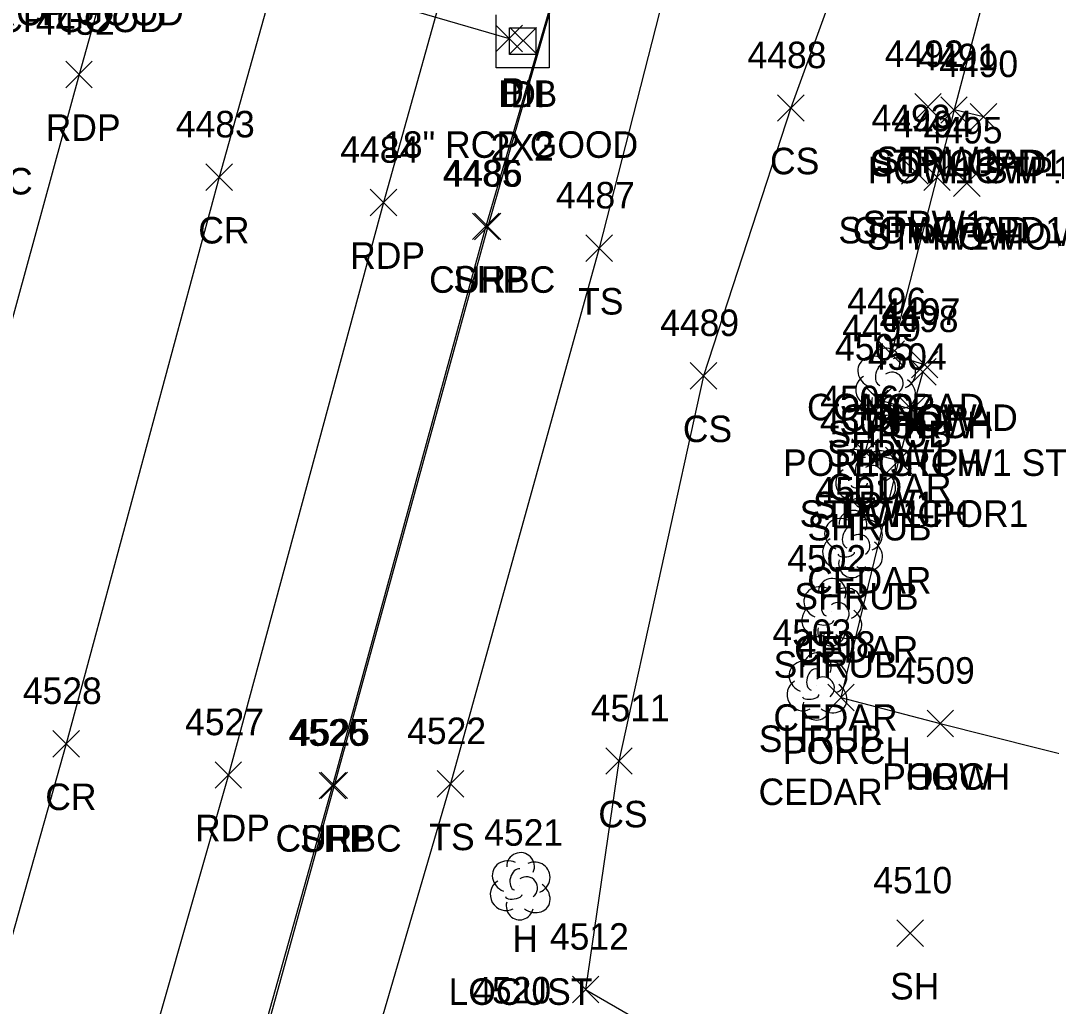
# Model space of a CAD drawing. Extents: x 1443912 to 1445411, y 621446 to 623693.
# Drawn here: x 1444910.4 to 1444988.1, y 623164.8 to 623239.1 of the extents above; entities that cross this region are included whole.
import ezdxf

# ---------------------------------------------------------------- set-up
doc = ezdxf.new("R2010")
doc.units = 0
for name, color, linetype in [('D_A', 7, 'Continuous'), ('D_C', 7, 'Continuous'), ('D_TIC', 7, 'Continuous'), ('DCP', 7, 'Continuous'), ('DS', 7, 'Continuous'), ('L_A', 7, 'Continuous'), ('L_C', 7, 'Continuous'), ('L_I', 7, 'Continuous'), ('L_TIC', 7, 'Continuous'), ('LBC', 7, 'Continuous'), ('LBF', 7, 'Continuous'), ('LELB', 7, 'Continuous'), ('LS', 7, 'Continuous'), ('LSH', 7, 'Continuous'), ('LTD', 7, 'Continuous'), ('P_A', 7, 'Continuous'), ('P_I', 7, 'Continuous'), ('P_TIC', 7, 'Continuous'), ('PET', 7, 'Continuous'), ('PRC', 7, 'Continuous'), ('PSP', 7, 'Continuous'), ('R_A', 7, 'Continuous'), ('R_I', 7, 'Continuous'), ('R_TIC', 7, 'Continuous'), ('RC', 7, 'Continuous')]:
    doc.layers.add(name, color=color, linetype=linetype)

msp = doc.modelspace()

# ---------------------------------------------------------------- linework, layer by layer
at = {"layer": 'D_TIC'}
for points in [[(1444946.257, 623236.76), (1444948.257, 623238.76)], [(1444948.257, 623236.76), (1444946.257, 623238.76)], [(1444947.315, 623236.598), (1444949.315, 623238.598)], [(1444949.315, 623236.598), (1444947.315, 623238.598)]]:
    msp.add_lwpolyline(points, dxfattribs=at)
at = {"layer": 'DCP'}
msp.add_lwpolyline([(1444912.99, 623247.747), (1444947.257, 623237.76)], dxfattribs=at)
at = {"layer": 'DS'}
for p, q in [((1444946.277, 623235.557), (1444946.277, 623239.557)), ((1444950.277, 623239.557), (1444950.277, 623235.557)), ((1444947.277, 623236.557), (1444947.277, 623238.557)), ((1444947.277, 623238.557), (1444949.277, 623238.557)), ((1444949.277, 623238.557), (1444949.277, 623236.557)), ((1444948.283, 623237.559), (1444948.283, 623237.559)), ((1444948.283, 623237.559), (1444948.283, 623237.559)), ((1444949.277, 623236.557), (1444947.277, 623236.557)), ((1444950.277, 623235.557), (1444946.277, 623235.557))]:
    msp.add_line(p, q, dxfattribs=at)
at = {"layer": 'L_TIC'}
for points in [[(1444967.484, 623231.521), (1444969.484, 623233.521)], [(1444969.484, 623231.521), (1444967.484, 623233.521)], [(1444977.831, 623231.611), (1444979.831, 623233.611)], [(1444979.831, 623231.611), (1444977.831, 623233.611)], [(1444979.793, 623231.369), (1444981.793, 623233.369)], [(1444981.793, 623231.369), (1444979.793, 623233.369)], [(1444979.793, 623231.369), (1444981.793, 623233.369)], [(1444981.793, 623231.369), (1444979.793, 623233.369)], [(1444982.02, 623230.85), (1444984.02, 623232.85)], [(1444984.02, 623230.85), (1444982.02, 623232.85)], [(1444982.02, 623230.85), (1444984.02, 623232.85)], [(1444984.02, 623230.85), (1444982.02, 623232.85)], [(1444976.835, 623226.768), (1444978.835, 623228.768)], [(1444978.835, 623226.768), (1444976.835, 623228.768)], [(1444978.509, 623226.308), (1444980.509, 623228.308)], [(1444980.509, 623226.308), (1444978.509, 623228.308)], [(1444978.509, 623226.308), (1444980.509, 623228.308)], [(1444980.509, 623226.308), (1444978.509, 623228.308)], [(1444980.755, 623225.845), (1444982.755, 623227.845)], [(1444982.755, 623225.845), (1444980.755, 623227.845)], [(1444980.755, 623225.845), (1444982.755, 623227.845)], [(1444982.755, 623225.845), (1444980.755, 623227.845)], [(1444953.045, 623220.944), (1444955.045, 623222.944)], [(1444955.045, 623220.944), (1444953.045, 623222.944)], [(1444975.062, 623212.967), (1444977.062, 623214.967)], [(1444977.062, 623212.967), (1444975.062, 623214.967)], [(1444977.578, 623212.165), (1444979.578, 623214.165)], [(1444979.578, 623212.165), (1444977.578, 623214.165)], [(1444977.578, 623212.165), (1444979.578, 623214.165)], [(1444979.578, 623212.165), (1444977.578, 623214.165)], [(1444960.908, 623211.324), (1444962.908, 623213.324)], [(1444962.908, 623211.324), (1444960.908, 623213.324)], [(1444977.439, 623211.62), (1444979.439, 623213.62)], [(1444979.439, 623211.62), (1444977.439, 623213.62)], [(1444977.439, 623211.62), (1444979.439, 623213.62)], [(1444979.439, 623211.62), (1444977.439, 623213.62)], [(1444974.156, 623209.478), (1444976.156, 623211.478)], [(1444976.156, 623209.478), (1444974.156, 623211.478)], [(1444976.627, 623208.775), (1444978.627, 623210.775)], [(1444978.627, 623208.775), (1444976.627, 623210.775)], [(1444976.627, 623208.775), (1444978.627, 623210.775)], [(1444978.627, 623208.775), (1444976.627, 623210.775)], [(1444973.096, 623205.579), (1444975.096, 623207.579)], [(1444975.096, 623205.579), (1444973.096, 623207.579)], [(1444975.619, 623204.932), (1444977.619, 623206.932)], [(1444977.619, 623204.932), (1444975.619, 623206.932)], [(1444975.619, 623204.932), (1444977.619, 623206.932)], [(1444977.619, 623204.932), (1444975.619, 623206.932)], [(1444971.269, 623187.062), (1444973.269, 623189.062)], [(1444973.269, 623187.062), (1444971.269, 623189.062)], [(1444978.759, 623185.106), (1444980.759, 623187.106)], [(1444980.759, 623185.106), (1444978.759, 623187.106)], [(1444978.759, 623185.106), (1444980.759, 623187.106)], [(1444980.759, 623185.106), (1444978.759, 623187.106)], [(1444954.534, 623182.272), (1444956.534, 623184.272)], [(1444956.534, 623182.272), (1444954.534, 623184.272)], [(1444941.825, 623180.553), (1444943.825, 623182.553)], [(1444943.825, 623180.553), (1444941.825, 623182.553)], [(1444976.485, 623169.293), (1444978.485, 623171.293)], [(1444978.485, 623169.293), (1444976.485, 623171.293)], [(1444952.019, 623165.045), (1444954.019, 623167.045)], [(1444954.019, 623165.045), (1444952.019, 623167.045)]]:
    msp.add_lwpolyline(points, dxfattribs=at)
at = {"layer": 'LBC'}
msp.add_lwpolyline([(1444979.759, 623186.106), (1444998.515, 623181.371)], dxfattribs=at)
at = {"layer": 'LBF'}
for points in [[(1444983.02, 623231.85), (1444980.793, 623232.369)], [(1444978.439, 623212.62), (1444977.627, 623209.775), (1444976.619, 623205.932), (1444972.269, 623188.062), (1444979.759, 623186.106)], [(1444977.627, 623209.775), (1444975.156, 623210.478), (1444974.096, 623206.579), (1444976.619, 623205.932)]]:
    msp.add_lwpolyline(points, dxfattribs=at)
at = {"layer": 'LELB'}
for points in [[(1445011.818, 623244.379), (1444995.904, 623251.684), (1444976.44, 623254.406), (1444961.702, 623251.968), (1444954.045, 623221.944), (1444942.825, 623181.553), (1444935.094, 623155.078), (1444941.304, 623148.676), (1444957.21, 623141.482), (1444982.161, 623136.484)], [(1444976.44, 623254.406), (1444968.484, 623232.521), (1444961.908, 623212.324), (1444955.534, 623183.272), (1444953.019, 623166.045), (1444969.926, 623156.274), (1444977.618, 623143.302)]]:
    msp.add_lwpolyline(points, dxfattribs=at)
at = {"layer": 'LS'}
msp.add_lwpolyline([(1444987.132, 623246.17), (1444984.639, 623246.949), (1444980.793, 623232.369), (1444979.509, 623227.308), (1444976.062, 623213.967), (1444978.578, 623213.165)], dxfattribs=at)
at = {"layer": 'LSH'}
for p, q in [((1444975.628, 623211.936), (1444975.628, 623211.936)), ((1444975.628, 623211.936), (1444975.628, 623211.936)), ((1444974.114, 623204.907), (1444974.114, 623204.907)), ((1444974.114, 623204.907), (1444974.114, 623204.907)), ((1444973.125, 623199.696), (1444973.125, 623199.696)), ((1444973.125, 623199.696), (1444973.125, 623199.696)), ((1444971.561, 623194.557), (1444971.561, 623194.557)), ((1444971.561, 623194.557), (1444971.561, 623194.557)), ((1444970.444, 623188.955), (1444970.444, 623188.955)), ((1444970.444, 623188.955), (1444970.444, 623188.955))]:
    msp.add_line(p, q, dxfattribs=at)
for centre in [(1444975.675, 623213.37), (1444974.161, 623206.341), (1444973.172, 623201.13), (1444971.607, 623195.991), (1444970.491, 623190.389)]:
    msp.add_arc(centre, 1.047, 335.52715, 180.95627, dxfattribs=at)
for centre, major_axis, ratio, start_param, end_param in [((1444974.836, 623212.602), (1.21, -0.512), 0.895232, 1.570796, 4.712389), ((1444976.669, 623212.519), (-1.141, -0.483), 0.949671, 1.570796, 4.712389), ((1444975.419, 623212.394), (-0.208, -0.792), 0.645439, 3.141593, 6.283185), ((1444974.545, 623211.227), (0.584, -1.042), 0.959034, 3.141593, 6.283185), ((1444976.128, 623211.769), (-0.5, 0.667), 0.989748, 3.141593, 6.283185), ((1444976.628, 623211.103), (-1.09, 0.792), 0.841452, 1.570796, 4.712389), ((1444975.628, 623210.436), (0.265, 1.061), 0.942809, 1.570796, 4.712389), ((1444975.17, 623211.186), (-0.625, -0.083), 0.423636, 0, 3.141593), ((1444973.323, 623205.573), (1.21, -0.512), 0.895232, 1.570796, 4.712389), ((1444975.156, 623205.49), (-1.141, -0.483), 0.949671, 1.570796, 4.712389), ((1444973.906, 623205.365), (-0.208, -0.792), 0.645439, 3.141593, 6.283185), ((1444973.031, 623204.198), (0.584, -1.042), 0.959034, 3.141593, 6.283185), ((1444974.614, 623204.74), (-0.5, 0.667), 0.989748, 3.141593, 6.283185), ((1444975.115, 623204.074), (-1.09, 0.792), 0.841452, 1.570796, 4.712389), ((1444974.115, 623203.407), (0.265, 1.061), 0.942809, 1.570796, 4.712389), ((1444973.656, 623204.157), (-0.625, -0.083), 0.423636, 0, 3.141593), ((1444972.333, 623200.362), (1.21, -0.512), 0.895232, 1.570796, 4.712389), ((1444974.167, 623200.279), (-1.141, -0.483), 0.949671, 1.570796, 4.712389), ((1444972.917, 623200.154), (-0.208, -0.792), 0.645439, 3.141593, 6.283185), ((1444972.042, 623198.987), (0.584, -1.042), 0.959034, 3.141593, 6.283185), ((1444973.625, 623199.529), (-0.5, 0.667), 0.989748, 3.141593, 6.283185), ((1444974.125, 623198.862), (-1.09, 0.792), 0.841452, 1.570796, 4.712389), ((1444972.667, 623198.945), (-0.625, -0.083), 0.423636, 0, 3.141593), ((1444973.125, 623198.196), (0.265, 1.061), 0.942809, 1.570796, 4.712389), ((1444970.769, 623195.223), (1.21, -0.512), 0.895232, 1.570796, 4.712389), ((1444971.352, 623195.015), (-0.208, -0.792), 0.645439, 3.141593, 6.283185), ((1444972.602, 623195.14), (-1.141, -0.483), 0.949671, 1.570796, 4.712389), ((1444972.061, 623194.39), (-0.5, 0.667), 0.989748, 3.141593, 6.283185), ((1444970.477, 623193.848), (0.584, -1.042), 0.959034, 3.141593, 6.283185), ((1444972.561, 623193.724), (-1.09, 0.792), 0.841452, 1.570796, 4.712389), ((1444971.102, 623193.807), (-0.625, -0.083), 0.423636, 0, 3.141593), ((1444971.561, 623193.057), (0.265, 1.061), 0.942809, 1.570796, 4.712389), ((1444969.652, 623189.622), (1.21, -0.512), 0.895232, 1.570796, 4.712389), ((1444971.485, 623189.539), (-1.141, -0.483), 0.949671, 1.570796, 4.712389), ((1444970.235, 623189.413), (-0.208, -0.792), 0.645439, 3.141593, 6.283185), ((1444970.944, 623188.789), (-0.5, 0.667), 0.989748, 3.141593, 6.283185), ((1444969.361, 623188.247), (0.584, -1.042), 0.959034, 3.141593, 6.283185), ((1444971.444, 623188.122), (-1.09, 0.792), 0.841452, 1.570796, 4.712389), ((1444969.986, 623188.205), (-0.625, -0.083), 0.423636, 0, 3.141593), ((1444970.444, 623187.455), (0.265, 1.061), 0.942809, 1.570796, 4.712389)]:
    msp.add_ellipse(centre, major_axis=major_axis, ratio=ratio, start_param=start_param, end_param=end_param, dxfattribs=at)
at = {"layer": 'LTD'}
msp.add_line((1444948.067, 623173.886), (1444948.067, 623173.886), dxfattribs=at)
msp.add_line((1444948.067, 623173.886), (1444948.067, 623173.886), dxfattribs=at)
msp.add_arc((1444948.114, 623175.32), 1.047, 335.52715, 180.95627, dxfattribs=at)
for centre, major_axis, ratio, start_param, end_param in [((1444947.275, 623174.552), (1.21, -0.512), 0.895232, 1.570796, 4.712389), ((1444949.109, 623174.469), (-1.141, -0.483), 0.949671, 1.570796, 4.712389), ((1444947.859, 623174.344), (-0.208, -0.792), 0.645439, 3.141593, 6.283185), ((1444946.984, 623173.177), (0.584, -1.042), 0.959034, 3.141593, 6.283185), ((1444948.567, 623173.719), (-0.5, 0.667), 0.989748, 3.141593, 6.283185), ((1444949.067, 623173.053), (-1.09, 0.792), 0.841452, 1.570796, 4.712389), ((1444948.067, 623172.386), (0.265, 1.061), 0.942809, 1.570796, 4.712389), ((1444947.609, 623173.136), (-0.625, -0.083), 0.423636, 0, 3.141593)]:
    msp.add_ellipse(centre, major_axis=major_axis, ratio=ratio, start_param=start_param, end_param=end_param, dxfattribs=at)
at = {"layer": 'P_TIC'}
for points in [[(1444913.827, 623234.039), (1444915.827, 623236.039)], [(1444915.827, 623234.039), (1444913.827, 623236.039)], [(1444924.386, 623226.302), (1444926.386, 623228.302)], [(1444926.386, 623226.302), (1444924.386, 623228.302)], [(1444936.78, 623224.39), (1444938.78, 623226.39)], [(1444938.78, 623224.39), (1444936.78, 623226.39)], [(1444944.503, 623222.598), (1444946.503, 623224.598)], [(1444946.503, 623222.598), (1444944.503, 623224.598)], [(1444912.851, 623183.574), (1444914.851, 623185.574)], [(1444914.851, 623183.574), (1444912.851, 623185.574)], [(1444925.085, 623181.222), (1444927.085, 623183.222)], [(1444927.085, 623181.222), (1444925.085, 623183.222)], [(1444932.942, 623180.42), (1444934.942, 623182.42)], [(1444934.942, 623180.42), (1444932.942, 623182.42)]]:
    msp.add_lwpolyline(points, dxfattribs=at)
at = {"layer": 'PET'}
for points in [[(1445036.702, 623677.704), (1445026.384, 623639.781), (1445008.648, 623576.155), (1444996.948, 623532.888), (1444979.777, 623472.466), (1444964.829, 623416.219), (1444955.709, 623382.545), (1444949.165, 623358.134), (1444939.286, 623323.432), (1444926.274, 623275.909), (1444914.827, 623235.039), (1444901.528, 623186.461), (1444892.14, 623152.692), (1444883.143, 623119.129), (1444870.129, 623073.226), (1444861.494, 623043.31), (1444850.844, 623006.823), (1444834.615, 622954.828), (1444817.277, 622898.327)], [(1445060.037, 623670.522), (1445049.49, 623631.423), (1445031.605, 623567.438), (1445020.437, 623527.05), (1445003.496, 623465.591), (1444988.101, 623409.137), (1444976.63, 623367.032), (1444962.485, 623315.052), (1444949.489, 623267.355), (1444937.78, 623225.39), (1444926.085, 623182.222), (1444915.481, 623145.054), (1444906.981, 623113.479), (1444893.635, 623066.096), (1444886.059, 623037.306), (1444876.58, 623001.084), (1444863.334, 622947.053), (1444849.426, 622890.74)]]:
    msp.add_lwpolyline(points, dxfattribs=at)
at = {"layer": 'PRC'}
msp.add_lwpolyline([(1445048.115, 623674.07), (1445038.049, 623635.877), (1445020.141, 623572.701), (1445008.5, 623529.106), (1444991.68, 623469.746), (1444976.214, 623412.438), (1444964.866, 623369.69), (1444950.638, 623318.466), (1444938.047, 623272.584), (1444925.386, 623227.302), (1444913.851, 623184.574), (1444903.742, 623148.669), (1444894.967, 623116.182), (1444881.802, 623068.916), (1444873.968, 623040.251), (1444864.099, 623005.335), (1444846.729, 622950.738), (1444829.368, 622896.11)], dxfattribs=at)
at = {"layer": 'PSP'}
msp.add_lwpolyline([(1444984.516, 623364.945), (1444970.172, 623313.004), (1444960.845, 623279.611), (1444959.914, 623275.87), (1444955.536, 623257.941), (1444945.503, 623223.598), (1444933.942, 623181.42), (1444927.821, 623159.658), (1444926.956, 623156.444), (1444922.102, 623137.709), (1444921.079, 623134.92), (1444914.496, 623111.784), (1444901.392, 623063.858), (1444892.119, 623031.221), (1444883.166, 622999.191), (1444870.024, 622952.196), (1444868.676, 622947.266), (1444864.214, 622931.668)], dxfattribs=at)
at = {"layer": 'R_TIC'}
for points in [[(1444944.638, 623222.583), (1444946.638, 623224.583)], [(1444946.638, 623222.583), (1444944.638, 623224.583)], [(1444933.06, 623180.442), (1444935.06, 623182.442)], [(1444935.06, 623180.442), (1444933.06, 623182.442)]]:
    msp.add_lwpolyline(points, dxfattribs=at)
at = {"layer": 'RC'}
msp.add_lwpolyline([(1444955.536, 623257.941), (1444945.638, 623223.583), (1444934.06, 623181.442), (1444928.035, 623159.578), (1444926.956, 623156.444)], dxfattribs=at)

# ---------------------------------------------------------------- texts
at = {"layer": 'D_A'}
for s, p in [('P', (1444946.635, 623232.76)), ('DIB', (1444946.417, 623232.598)), ('DI', (1444947.338, 623232.559))]:
    msp.add_text(s, height=2, dxfattribs=at).set_placement(p)
at = {"layer": 'D_C'}
for s, p in [('18" RCP GOOD', (1444902.06, 623238.238)), ('18" RCP GOOD', (1444903.487, 623238.747)), ('18" RCP GOOD', (1444937.753, 623228.76)), ('2X2', (1444945.857, 623228.559))]:
    msp.add_text(s, height=2, dxfattribs=at).set_placement(p)
at = {"layer": 'L_A'}
for s, p in [('CS', (1444966.925, 623227.521)), ('STP1 CPD1', (1444974.432, 623227.369)), ('CONCPAD', (1444974.439, 623227.369)), ('STPW1', (1444974.894, 623227.611)), ('HOW1 STP1 ST', (1444974.288, 623226.85)), ('HOW', (1444980.406, 623226.85)), ('STPW1', (1444973.898, 623222.768)), ('STPW1 CPD1', (1444972.076, 623222.308)), ('CONCPAD', (1444973.155, 623222.308)), ('STPW1 HOW1', (1444974.212, 623221.845)), ('HOW', (1444979.141, 623221.845)), ('TS', (1444952.455, 623216.944)), ('CONCPAD', (1444969.708, 623208.967)), ('CONCPAD', (1444972.224, 623208.165)), ('HOW', (1444975.964, 623208.165)), ('CS', (1444960.349, 623207.324)), ('PORCH', (1444974.061, 623207.62)), ('HOW', (1444975.825, 623207.62)), ('SHRUB', (1444971.258, 623206.936)), ('STPW1', (1444971.219, 623205.478)), ('POR1 STPW1 ST', (1444967.903, 623204.775)), ('PORCH', (1444973.249, 623204.775)), ('STPW1', (1444970.159, 623201.579)), ('STPW1 POR1', (1444969.155, 623200.932)), ('PORCH', (1444972.241, 623200.932)), ('SHRUB', (1444969.744, 623199.907)), ('SHRUB', (1444968.755, 623194.696)), ('SHRUB', (1444967.191, 623189.557)), ('SHRUB', (1444966.074, 623183.955)), ('PORCH', (1444967.891, 623183.062)), ('PORCH', (1444975.381, 623181.106)), ('HOW', (1444977.145, 623181.106)), ('CS', (1444953.975, 623178.272)), ('TS', (1444941.235, 623176.553)), ('H', (1444947.5, 623168.886)), ('SH', (1444975.973, 623165.293))]:
    msp.add_text(s, height=2, dxfattribs=at).set_placement(p)
at = {"layer": 'L_C'}
for s, p in [('CEDAR', (1444971.242, 623202.936)), ('CEDAR', (1444969.729, 623195.907)), ('CEDAR', (1444968.739, 623190.696)), ('CEDAR', (1444967.175, 623185.557)), ('CEDAR', (1444966.058, 623179.955)), ('LOCUST', (1444942.689, 623164.886))]:
    msp.add_text(s, height=2, dxfattribs=at).set_placement(p)
at = {"layer": 'L_I'}
for s, p in [('4488', (1444965.225, 623235.521)), ('4492', (1444975.572, 623235.611)), ('4491', (1444978.101, 623235.369)), ('4491', (1444978.101, 623235.369)), ('4490', (1444979.674, 623234.85)), ('4490', (1444979.674, 623234.85)), ('4493', (1444974.575, 623230.768)), ('4494', (1444976.249, 623230.308)), ('4494', (1444976.249, 623230.308)), ('4495', (1444978.495, 623229.845)), ('4495', (1444978.495, 623229.845)), ('4487', (1444950.785, 623224.944)), ('4496', (1444972.747, 623216.967)), ('4498', (1444975.18, 623215.62)), ('4498', (1444975.18, 623215.62)), ('4497', (1444975.319, 623216.165)), ('4497', (1444975.319, 623216.165)), ('4489', (1444958.64, 623215.324)), ('4499', (1444972.36, 623214.936)), ('4505', (1444971.818, 623213.478)), ('4504', (1444974.289, 623212.775)), ('4504', (1444974.289, 623212.775)), ('4506', (1444970.703, 623209.579)), ('4507', (1444973.281, 623208.932)), ('4507', (1444973.281, 623208.932)), ('4500', (1444970.689, 623207.907)), ('4501', (1444970.353, 623202.696)), ('4502', (1444968.222, 623197.557)), ('4503', (1444967.105, 623191.955)), ('4508', (1444968.931, 623191.062)), ('4509', (1444976.413, 623189.106)), ('4509', (1444976.413, 623189.106)), ('4511', (1444953.408, 623186.272)), ('4522', (1444939.566, 623184.553)), ('4521', (1444945.374, 623176.886)), ('4510', (1444974.706, 623173.293)), ('4512', (1444950.327, 623169.045)), ('4520', (1444944.468, 623164.992))]:
    msp.add_text(s, height=2, dxfattribs=at).set_placement(p)
at = {"layer": 'P_A'}
for s, p in [('RDP', (1444912.315, 623230.039)), ('CR', (1444923.819, 623222.302)), ('RDP', (1444935.269, 623220.39)), ('SHP', (1444943.039, 623218.598)), ('CR', (1444912.284, 623179.574)), ('RDP', (1444923.573, 623177.222)), ('SHP', (1444931.477, 623176.42))]:
    msp.add_text(s, height=2, dxfattribs=at).set_placement(p)
at = {"layer": 'P_I'}
for s, p in [('4432', (1444911.567, 623238.039)), ('4483', (1444922.126, 623230.302)), ('4484', (1444934.521, 623228.39)), ('4485', (1444942.244, 623226.598)), ('4528', (1444910.591, 623187.574)), ('4527', (1444922.826, 623185.222)), ('4526', (1444930.627, 623184.42))]:
    msp.add_text(s, height=2, dxfattribs=at).set_placement(p)
at = {"layer": 'R_A'}
for p in [(1444901.826, 623225.997), (1444941.221, 623218.583), (1444929.643, 623176.442)]:
    msp.add_text('CURBC', height=2, dxfattribs=at).set_placement(p)
at = {"layer": 'R_I'}
for s, p in [('4486', (1444942.323, 623226.583)), ('4525', (1444930.801, 623184.442))]:
    msp.add_text(s, height=2, dxfattribs=at).set_placement(p)

doc.saveas('drawing.dxf')
